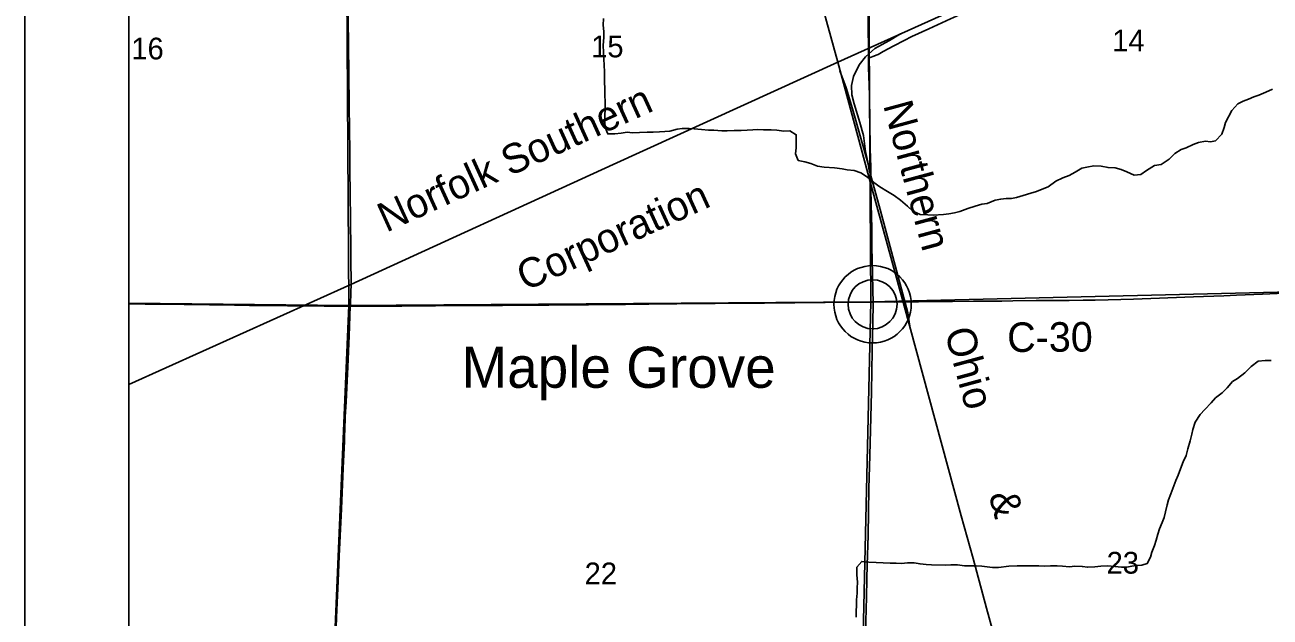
# Model space of a CAD drawing. Extents: x 0 to 34, y 0 to 22.
# Drawn here: x 2 to 3.198, y 18.94 to 19.51 of the extents above; entities that cross this region are included whole.
import ezdxf

# ---------------------------------------------------------------- set-up
doc = ezdxf.new("R2010")
doc.units = 0
for name, color, linetype in [('GM_X_Corporation', 7, 'Continuous'), ('GM_X_County_Road', 7, 'Continuous'), ('GM_X_County_Road_Text', 7, 'Continuous'), ('GM_X_Minor_River', 7, 'Continuous'), ('GM_X_Rail_Line', 7, 'Continuous'), ('GM_X_Rail_Line_Text', 7, 'Continuous'), ('GM_X_Section_Text', 7, 'Continuous'), ('GM_X_Township_Road', 7, 'Continuous'), ('GM_X_Unincorporated', 7, 'Continuous'), ('GM_X_Unincorporated_Location', 7, 'Continuous'), ('GM_X_Unincorporated_Text', 7, 'Continuous'), ('SH_Data', 7, 'Continuous')]:
    doc.layers.add(name, color=color, linetype=linetype)

msp = doc.modelspace()

# ---------------------------------------------------------------- linework, layer by layer
at = {"layer": 'GM_X_Corporation'}
for points in [[(2.1, 20.7197), (2.1, 14.1)], [(2.1, 20.7197), (2.1, 17.7319)]]:
    msp.add_lwpolyline(points, dxfattribs=at)
for points in [[(3.313, 19.7571), (3.3128, 19.2554), (2.8138, 19.2434), (2.8104, 19.7478)], [(2.1, 19.7448), (2.1, 19.2421), (2.3115, 19.2398), (2.3085, 19.745)], [(2.8104, 19.7478), (2.8138, 19.2434), (2.3115, 19.2398), (2.3085, 19.745)], [(2.8138, 19.2434), (3.3128, 19.2554), (3.2999, 18.7516), (2.8021, 18.7416)], [(2.1, 19.2421), (2.1, 18.7363), (2.2901, 18.7344), (2.3115, 19.2398)], [(2.3115, 19.2398), (2.8138, 19.2434), (2.8021, 18.7416), (2.2901, 18.7344)]]:
    msp.add_lwpolyline(points, close=True, dxfattribs=at)
at = {"layer": 'GM_X_County_Road'}
for points in [[(2.313, 19.2392), (2.3131, 19.2414), (2.3135, 19.2517), (2.3137, 19.261), (2.3137, 19.2669), (2.3136, 19.2787), (2.3136, 19.2927), (2.3132, 19.3234), (2.313, 19.3467), (2.3127, 19.3713), (2.3124, 19.3881), (2.312, 19.4316), (2.3115, 19.4633), (2.3108, 19.5155), (2.3104, 19.555), (2.3101, 19.5652), (2.3096, 19.6156), (2.3092, 19.6582), (2.309, 19.6768), (2.3087, 19.706), (2.3084, 19.7275), (2.3082, 19.7435)], [(2.8115, 19.4777), (2.8113, 19.4871), (2.8111, 19.5072), (2.8109, 19.5349), (2.8105, 19.5598), (2.8104, 19.5812), (2.8101, 19.5961), (2.8099, 19.6195), (2.8097, 19.639), (2.8092, 19.6713), (2.8087, 19.7146), (2.8083, 19.7388), (2.8082, 19.7459)], [(2.8115, 19.4777), (2.8183, 19.4804), (2.8189, 19.4806), (2.8206, 19.4814), (2.8256, 19.4841), (2.8359, 19.4897), (2.8456, 19.4948), (2.8531, 19.4985), (2.8695, 19.5059), (2.8904, 19.5155), (2.9366, 19.5363), (2.9553, 19.5447), (2.9714, 19.552), (2.9955, 19.5629), (3.0298, 19.5784), (3.0561, 19.5903), (3.0793, 19.6008), (3.0958, 19.6082), (3.1187, 19.6186), (3.1368, 19.6268), (3.151, 19.6332), (3.162, 19.6383), (3.1784, 19.6456), (3.1997, 19.6553)], [(2.8158, 19.2432), (2.8156, 19.2543), (2.8153, 19.2705), (2.8148, 19.2963), (2.8145, 19.3143), (2.814, 19.337), (2.8136, 19.3525), (2.8137, 19.3637), (2.8136, 19.373), (2.8132, 19.3907), (2.8125, 19.4414), (2.8122, 19.452), (2.8116, 19.4685), (2.8115, 19.4759), (2.8115, 19.4777)], [(2.8158, 19.2432), (2.8256, 19.2433), (2.8362, 19.2432), (2.8595, 19.2435), (2.8729, 19.2437), (2.8922, 19.2437), (2.9124, 19.2439), (2.9226, 19.244), (2.9397, 19.2441), (2.9503, 19.2443), (2.9726, 19.2446), (2.9922, 19.2447), (3.0044, 19.2447), (3.018, 19.2449), (3.0295, 19.2451), (3.0419, 19.2454), (3.0662, 19.2459), (3.0829, 19.2466), (3.1239, 19.2482), (3.1531, 19.2493), (3.1654, 19.2498), (3.1903, 19.2507), (3.2902, 19.2552)], [(2.2921, 18.7341), (2.2929, 18.7557), (2.2936, 18.7728), (2.2946, 18.7998), (2.2951, 18.8132), (2.2958, 18.8346), (2.2973, 18.8731), (2.2981, 18.8967), (2.2991, 18.9197), (2.2998, 18.9402), (2.3014, 18.9747), (2.3023, 18.9989), (2.3044, 19.0442), (2.3061, 19.0834), (2.3073, 19.1095), (2.3078, 19.1256), (2.3079, 19.1272), (2.3082, 19.1327), (2.3089, 19.1473), (2.3105, 19.1809), (2.3118, 19.2107), (2.313, 19.2392)], [(2.8034, 18.7413), (2.8039, 18.7512), (2.8053, 18.7937), (2.8058, 18.8177), (2.8074, 18.8727), (2.8081, 18.9034), (2.809, 18.9364), (2.8095, 18.9594), (2.81, 18.9768), (2.8103, 18.9904), (2.811, 19.0187), (2.8119, 19.0638), (2.8127, 19.0955), (2.8142, 19.1567), (2.815, 19.1965), (2.8156, 19.2229), (2.8159, 19.2419), (2.8158, 19.2432)]]:
    msp.add_lwpolyline(points, dxfattribs=at)
at = {"layer": 'GM_X_Minor_River'}
for points in [[(2.73, 19.4076), (2.7234, 19.4084), (2.7177, 19.4088), (2.7103, 19.4088), (2.7048, 19.4091), (2.7001, 19.4087), (2.6946, 19.4084), (2.6891, 19.4082), (2.6821, 19.4082), (2.6755, 19.4077), (2.6705, 19.4077), (2.6626, 19.4084), (2.6577, 19.4084), (2.6509, 19.409), (2.6439, 19.4096), (2.6389, 19.4102), (2.6321, 19.41), (2.6274, 19.4095), (2.6205, 19.4075), (2.6156, 19.4073), (2.6105, 19.4069), (2.6042, 19.4066), (2.5984, 19.4064), (2.5912, 19.4063), (2.5844, 19.4058), (2.5792, 19.4064), (2.5736, 19.4056), (2.5675, 19.4049), (2.5607, 19.4048), (2.5581, 19.4111), (2.5577, 19.4169), (2.5578, 19.4228), (2.5582, 19.4283), (2.558, 19.4361), (2.5579, 19.4418), (2.5577, 19.449), (2.5576, 19.4543), (2.5576, 19.4646), (2.5573, 19.471), (2.557, 19.4767), (2.5564, 19.4836), (2.5563, 19.49), (2.5569, 19.4978), (2.5569, 19.5033), (2.5562, 19.5096), (2.5564, 19.5159)], [(3.2002, 19.4479), (3.1937, 19.4449), (3.1869, 19.4421), (3.1821, 19.4404), (3.1768, 19.4384), (3.1719, 19.4365), (3.1668, 19.4337), (3.1609, 19.4275), (3.1549, 19.4157), (3.1536, 19.411), (3.1514, 19.4045), (3.1453, 19.3983), (3.1404, 19.3972), (3.1355, 19.3978), (3.1288, 19.3967), (3.1237, 19.3948), (3.1171, 19.3916), (3.1123, 19.3898), (3.1062, 19.386), (3.1007, 19.3807), (3.0931, 19.3753), (3.0865, 19.3746), (3.0789, 19.3698), (3.0735, 19.3657), (3.0671, 19.3652), (3.0599, 19.3684), (3.0544, 19.3706), (3.0486, 19.3723), (3.0419, 19.3725), (3.0353, 19.3737), (3.0281, 19.3741), (3.0215, 19.373), (3.0166, 19.3719), (3.0103, 19.368), (3.0046, 19.365), (2.9983, 19.3625), (2.9917, 19.3593), (2.9842, 19.3541), (2.9784, 19.3516), (2.973, 19.3496), (2.9675, 19.3479), (2.9601, 19.3457), (2.9537, 19.3438), (2.949, 19.3429), (2.944, 19.3427), (2.9387, 19.3422), (2.9334, 19.3411), (2.9256, 19.3379), (2.9203, 19.3374), (2.9139, 19.3355), (2.907, 19.3331), (2.8994, 19.3303), (2.8943, 19.329), (2.8888, 19.3281), (2.8835, 19.3275), (2.8737, 19.3268), (2.8684, 19.327), (2.861, 19.3275), (2.854, 19.3307), (2.8491, 19.3353), (2.8423, 19.341), (2.8361, 19.3458), (2.8297, 19.3495), (2.8225, 19.3541), (2.8167, 19.3583), (2.8106, 19.3633), (2.804, 19.3673), (2.7976, 19.3698), (2.791, 19.3702), (2.786, 19.3714), (2.7787, 19.3722), (2.7688, 19.373), (2.7624, 19.374), (2.756, 19.3765), (2.7501, 19.378), (2.7439, 19.3794), (2.7412, 19.3857), (2.7419, 19.3914), (2.7419, 19.4041), (2.7357, 19.4079), (2.73, 19.4076)], [(3.1988, 19.1871), (3.1929, 19.1869), (3.1864, 19.1864), (3.1796, 19.1811), (3.1733, 19.1751), (3.1664, 19.1698), (3.1617, 19.1668), (3.1565, 19.1606), (3.1516, 19.1559), (3.1453, 19.1512), (3.1409, 19.1461), (3.1348, 19.1398), (3.1306, 19.1349), (3.1258, 19.1275), (3.1235, 19.1207), (3.1224, 19.116), (3.1208, 19.1097), (3.1185, 19.102), (3.1171, 19.0957), (3.1142, 19.0894), (3.1115, 19.0828), (3.1092, 19.0766), (3.1071, 19.0716), (3.1021, 19.0588)], [(3.1021, 19.0588), (3.1, 19.0531), (3.0986, 19.0483), (3.0971, 19.0413), (3.0957, 19.036), (3.0938, 19.0311), (3.0915, 19.025), (3.0899, 19.0201), (3.088, 19.0141), (3.0865, 19.0091), (3.0841, 19.0027), (3.0828, 18.9978), (3.0795, 18.9917), (3.0742, 18.99), (3.0693, 18.9899), (3.0646, 18.9891), (3.0598, 18.9882), (3.0547, 18.9881), (3.0485, 18.9887), (3.0413, 18.9895), (3.035, 18.9893), (3.0291, 18.9886), (3.0223, 18.9881), (3.017, 18.989), (3.01, 18.9891), (3.0049, 18.9885), (2.9981, 18.9891), (2.9928, 18.9896), (2.9865, 18.9896), (2.9806, 18.9892), (2.9752, 18.9895), (2.9592, 18.9896), (2.9543, 18.9894), (2.9464, 18.9891), (2.9365, 18.988), (2.9308, 18.988), (2.9257, 18.9884), (2.9204, 18.9892), (2.9149, 18.9896), (2.91, 18.9895), (2.9039, 18.9895), (2.8971, 18.9903), (2.8905, 18.9905), (2.8858, 18.9902), (2.8719, 18.9903), (2.8668, 18.9909), (2.8611, 18.9913), (2.8555, 18.9923), (2.849, 18.9923), (2.8432, 18.9918), (2.8382, 18.992), (2.8324, 18.9922), (2.8254, 18.9924), (2.8189, 18.9927), (2.8117, 18.9931), (2.8049, 18.9937), (2.8003, 18.9882), (2.8001, 18.9808), (2.8008, 18.9738), (2.8006, 18.9679), (2.8004, 18.9631), (2.7998, 18.9567), (2.7999, 18.952), (2.7997, 18.9453), (2.7996, 18.9402)]]:
    msp.add_lwpolyline(points, dxfattribs=at)
at = {"layer": 'GM_X_Rail_Line'}
for points in [[(2.938, 18.901), (2.925, 18.9487), (2.912, 18.9966), (2.9007, 19.0375), (2.8448, 19.2429), (2.8141, 19.3553), (2.7818, 19.4739), (2.7266, 19.6749), (2.6668, 19.8949), (2.6541, 19.9413), (2.6331, 20.0177), (2.6112, 20.0978), (2.5504, 20.3216), (2.4973, 20.5157), (2.4921, 20.5336), (2.4852, 20.5546), (2.4705, 20.591), (2.4582, 20.618), (2.4159, 20.7121), (2.4158, 20.7122)], [(2.1, 19.1638), (2.3136, 19.2601), (2.5658, 19.3753), (2.7818, 19.4739), (3.0198, 19.5813), (3.1145, 19.6242), (3.2034, 19.6645), (3.242, 19.6819), (3.8143, 19.9407), (4.0482, 20.0467), (4.1489, 20.0916), (4.3092, 20.1646)], [(2.8423, 19.5012), (2.8317, 19.4946), (2.8176, 19.4871), (2.8086, 19.4791), (2.8024, 19.4712), (2.7971, 19.4602), (2.795, 19.4514), (2.7955, 19.4426), (2.7976, 19.4337), (2.803, 19.416), (2.8065, 19.4034), (2.8087, 19.3881), (2.8113, 19.3749)], [(2.8113, 19.3749), (2.7959, 19.4289), (2.7901, 19.4493), (2.784, 19.4656)], [(2.8113, 19.3749), (2.8119, 19.3715), (2.8228, 19.3321), (2.8494, 19.2329), (2.8516, 19.2178)]]:
    msp.add_lwpolyline(points, dxfattribs=at)
at = {"layer": 'GM_X_Township_Road'}
for points in [[(2.8158, 19.2432), (2.8256, 19.2433), (2.8362, 19.2432), (2.8595, 19.2435), (2.8729, 19.2437), (2.8922, 19.2437), (2.9124, 19.2439), (2.9226, 19.244), (2.9397, 19.2441), (2.9503, 19.2443), (2.9726, 19.2446), (2.9922, 19.2447), (3.0044, 19.2447), (3.018, 19.2449), (3.0295, 19.2451), (3.0419, 19.2454), (3.0662, 19.2459), (3.0829, 19.2466), (3.1239, 19.2482), (3.1531, 19.2493), (3.1654, 19.2498), (3.1903, 19.2507), (3.2902, 19.2552)], [(2.1, 19.2414), (2.1158, 19.2412), (2.1531, 19.2407), (2.2016, 19.2402), (2.2159, 19.24), (2.2411, 19.2397), (2.2525, 19.2396), (2.2594, 19.2395), (2.2653, 19.2394), (2.288, 19.2392), (2.3036, 19.2392), (2.313, 19.2392)], [(2.313, 19.2392), (2.3171, 19.2392), (2.3361, 19.2392), (2.3625, 19.2393), (2.3951, 19.2395), (2.4132, 19.2397), (2.4402, 19.2398), (2.453, 19.2399), (2.4595, 19.24), (2.4673, 19.2401), (2.4865, 19.2402), (2.504, 19.2403), (2.5276, 19.2405), (2.5422, 19.2406), (2.5596, 19.2407), (2.5708, 19.2408), (2.573, 19.2408), (2.5776, 19.2409), (2.6, 19.2411), (2.6271, 19.2414), (2.6641, 19.2417), (2.6858, 19.242), (2.7113, 19.2422), (2.7698, 19.2427), (2.7962, 19.243), (2.8123, 19.2432), (2.8158, 19.2432)]]:
    msp.add_lwpolyline(points, dxfattribs=at)
at = {"layer": 'GM_X_Unincorporated'}
for radius in [0.0372, 0.0236]:
    msp.add_circle((2.8154, 19.241), radius, dxfattribs=at)
at = {"layer": 'GM_X_Unincorporated_Location'}
msp.add_line((2.8154, 19.241), (2.8154, 19.241), dxfattribs=at)
at = {"layer": 'SH_Data'}
for p, q in [((2, 21), (2, 14)), ((2.1, 20.9), (2.1, 14.1))]:
    msp.add_line(p, q, dxfattribs=at)

# ---------------------------------------------------------------- texts
at = {"layer": 'GM_X_County_Road_Text'}
msp.add_text('C-30', height=0.02841, rotation=0.3422, dxfattribs=at).set_placement((2.9449, 19.1951))
at = {"layer": 'GM_X_Rail_Line_Text'}
for s, height, rotation, p in [('Norfolk Southern', 0.028314, 24.498, (2.3476, 19.3098)), ('Northern', 0.02831, 285.1426, (2.8254, 19.4326)), ('Corporation', 0.028314, 24.6113, (2.4814, 19.2533)), ('Ohio', 0.02831, 285.1641, (2.8845, 19.2149)), ('&', 0.0283, 285.311, (2.9269, 19.0576))]:
    msp.add_text(s, height=height, rotation=rotation, dxfattribs=at).set_placement(p)
at = {"layer": 'GM_X_Section_Text'}
for s, p in [('15', (2.5447, 19.4785)), ('14', (3.0459, 19.4842)), ('16', (2.1024, 19.4765)), ('23', (3.0405, 18.982)), ('22', (2.5384, 18.9717))]:
    msp.add_text(s, height=0.02093, rotation=0, dxfattribs=at).set_placement(p)
at = {"layer": 'GM_X_Unincorporated_Text'}
msp.add_text('Maple Grove', height=0.039489, rotation=0, dxfattribs=at).set_placement((2.4199, 19.1607))

doc.saveas('drawing.dxf')
